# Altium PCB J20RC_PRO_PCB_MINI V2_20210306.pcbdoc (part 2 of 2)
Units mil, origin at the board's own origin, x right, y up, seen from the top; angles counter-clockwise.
Board outline 5082.94 x 4658.14 mil, 2 copper layers (Top Layer, Bottom Layer); 108 components, 96 nets, 409 pads, 123 vias.
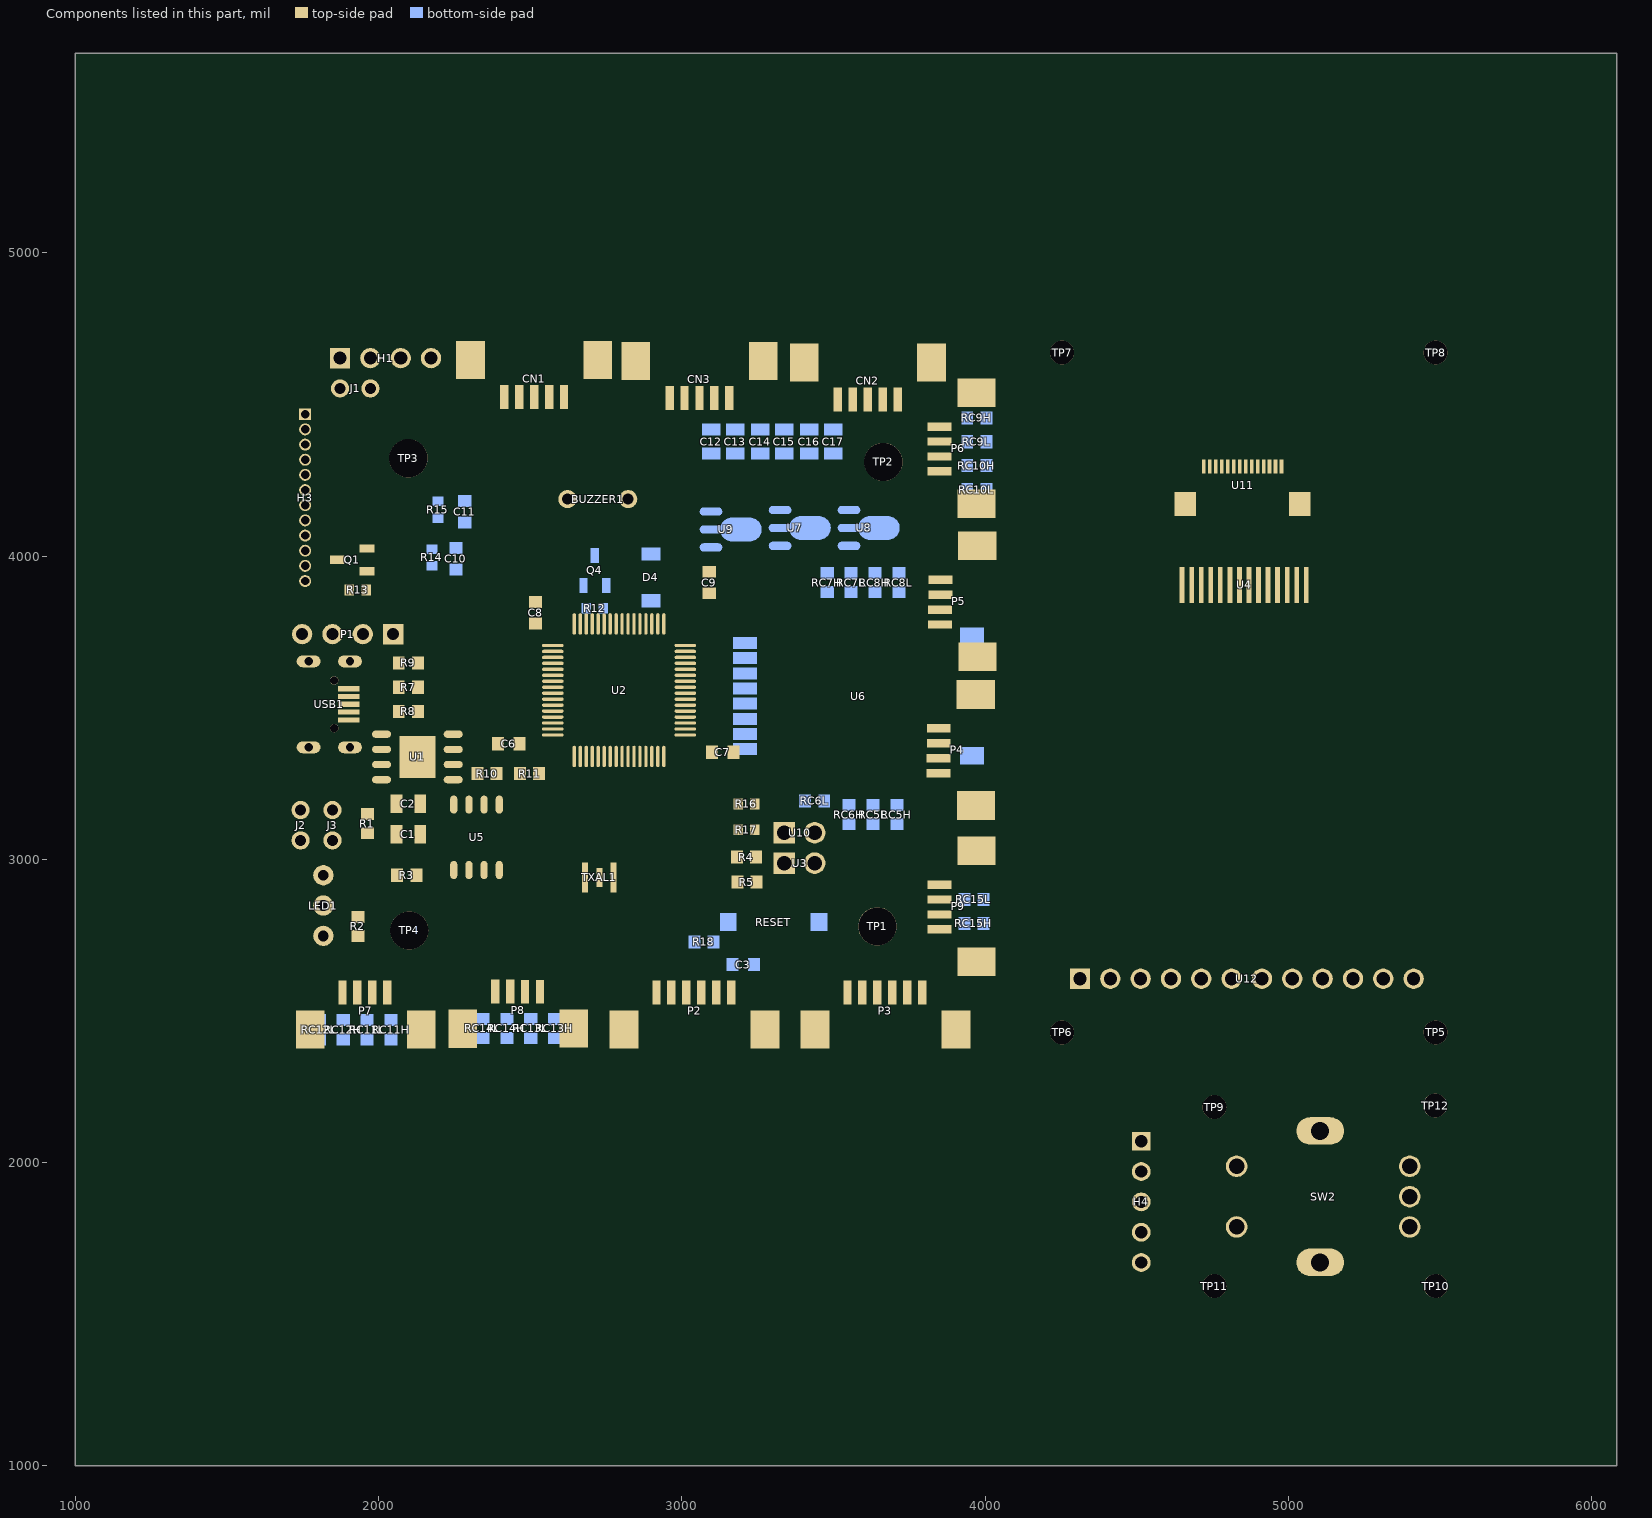
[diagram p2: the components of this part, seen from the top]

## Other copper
Top Layer:
  region net R2_1: 1840.52,2772.75 1840.29,2722.56 1863.8,2742.55 1863.85,2752.55
  region net R3_1: 1840.41,2972.85 1840.4,2922.65 1863.83,2942.75 1863.83,2952.75
  region net U1_5: 1763.11,3185.26 1763.11,3140.26 1784.11,3157.76 1784.11,3167.76
  region net U1_5: 1828.43,3140.26 1828.42,3185.26 1807.42,3167.76 1807.43,3157.76
  region net PPM: 1993.12,4575.25 1993.11,4530.25 2014.11,4547.75 2014.11,4557.75
  region net LCD_A0: 1771.29,4182.52 1771.28,4152.99 1785.07,4162.75 1785.07,4172.75
  region net LCD_SDA: 1771.29,4232.52 1771.28,4202.99 1785.07,4212.75 1785.07,4222.75
  region net LCD_SCK: 1771.29,4282.52 1771.28,4252.99 1785.07,4262.75 1785.07,4272.75
  region net LCD_CS: 1771.29,4432.52 1771.28,4402.99 1785.07,4412.75 1785.07,4422.75
  region net LCD_RST: 1771.29,4132.52 1771.28,4102.99 1785.07,4112.75 1785.07,4122.75
  region net LCD_LED-: 1771.29,3982.52 1771.28,3952.99 1785.07,3962.75 1785.07,3972.75
  region net VCC_MCU: 3461.71,3114.33 3461.7,3061.18 3486.51,3082.76 3486.51,3092.76
  region net VCC_LCD: 2845.77,4207.6 2800.77,4207.6 2818.27,4228.6 2828.27,4228.6
  region net 2SL: 3104.27,3100.69 3122.27,3100.69 3118.27,3109.09 3108.27,3109.09
  region net 2SL: 3125.24,3093.5 3112.51,3080.78 3121.28,3077.67 3128.35,3084.73
  region net 2SL: 2999.01,3239.73 2986.29,3227 2983.18,3235.77 2990.24,3242.84
  region net 1SL: 3174.27,2919.82 3192.27,2919.82 3188.27,2911.42 3178.27,2911.42
  region net 1SL: 2942.14,3444.7 2931.56,3430.14 2927.08,3438.27 2933.03,3446.46
  region net CH16: 2820.34,3393.75 2820.33,3411.75 2811.93,3407.75 2811.93,3397.75
  region net CH16: 3044.27,3249.82 3062.27,3249.82 3058.27,3241.42 3048.27,3241.42
  region net NRF_IRQ: 3200.34,3654.46 3200.32,3672.46 3191.92,3668.45 3191.94,3658.45
  region net NRF_CE: 3379.02,3630.78 3366.29,3643.5 3363.18,3634.73 3370.26,3627.67
  region net NRF_MISO: 2889.27,3595.69 2907.27,3595.69 2903.27,3604.09 2893.27,3604.09
  region net NRF_MOSI: 2885.24,3617 2872.52,3629.73 2878.33,3629.89 2885.4,3622.81
  region net NRF_SCK: 2914.27,3645.69 2932.27,3645.69 2928.27,3654.09 2918.27,3654.09
  region net NRF_CSN: 2936.65,3685.76 2952.69,3693.91 2945.87,3699.86 2935.87,3694.78
  region net RX_BM_SW: 3024.02,4200.78 3011.29,4213.5 3008.18,4204.73 3015.26,4197.67
  region net RX_BM_SW: 3094.27,4280.69 3112.27,4280.69 3108.27,4289.09 3098.27,4289.09
  region net EEPROM_SCL: 2390.52,3270.78 2377.78,3283.5 2374.68,3274.73 2381.75,3267.66
  region net EEPROM_SCL: 2421.16,3459.57 2419.88,3477.53 2428.54,3474.15 2429.25,3464.15
  region net BM_CLK: 2194.27,3834.82 2212.27,3834.82 2208.27,3826.42 2198.27,3826.42
  region net VCC_MCU: 2640.24,3983.5 2627.51,3970.78 2636.28,3967.67 2643.35,3974.74
  region net SWDIO: 2680.24,3682 2667.52,3694.73 2676.29,3697.84 2683.36,3690.77
  region net USB_DP: 2680.24,3647 2667.52,3659.73 2676.29,3662.84 2683.36,3655.77
  region net USB_DM: 2680.24,3612 2667.52,3624.73 2676.29,3627.84 2683.36,3620.77
  region net SWCLK: 2456.21,3731.75 2456.2,3713.75 2464.6,3717.75 2464.61,3727.75
  region net LCD_LED: 2449.56,3428.26 2449.52,3446.26 2441.13,3442.25 2441.15,3432.25
  region net LCD_LED: 2673.21,3451.04 2655.36,3448.73 2660.37,3440.91 2670.37,3442.2
  region net BEEPER: 2749.02,3435.78 2736.29,3448.5 2733.18,3439.73 2740.26,3432.67
  region net U1_7: 2203.92,2907.19 2191.17,2919.9 2188.07,2911.13 2195.16,2904.07
  region net +5V: 2256.28,3421.69 2238.41,3419.59 2241.37,3428.4 2251.37,3429.57
  region net U1_5: 2011.21,3236.75 2011.2,3218.75 2019.6,3222.75 2019.61,3232.75
  region net VM: 3438.46,3573.75 3432.96,3556.61 3426.11,3562.75 3429.32,3572.75
  region net VM: 3438.46,3573.75 3432.96,3556.61 3426.11,3562.75 3429.32,3572.75
  region net VM: 3248.42,3176.35 3230.64,3173.49 3235.87,3165.82 3245.87,3167.43
  region net BM_CLK: 2968,4244.77 2950.09,4246.54 2954.87,4254.51 2964.87,4253.52
  region net CH15: 3074.27,3269.82 3092.27,3269.82 3088.27,3261.42 3078.27,3261.42
  region net CH15: 2909.27,3495.69 2927.27,3495.69 2923.27,3504.09 2913.27,3504.09
  region net BAT+: 3658.76,4100.69 3640.76,4100.7 3644.76,4109.1 3654.76,4109.09
  region net BAT+: 3658.26,4173.18 3640.29,4172.14 3644.76,4163.99 3654.76,4164.57
  region net CH8: 3840.34,3863.75 3840.33,3881.75 3831.93,3877.75 3831.93,3867.75
  region net CH7: 3843.93,3814.45 3843.92,3832.45 3835.53,3828.45 3835.53,3818.45
  region net CH10: 3840.34,4368.75 3840.33,4386.75 3831.93,4382.75 3831.93,4372.75
  region net CH9: 3942.01,4365.06 3929.28,4377.79 3926.17,4369.02 3933.24,4361.95
  region net CH9: 3950.26,4369.11 3932.26,4369.09 3936.27,4360.7 3946.27,4360.7
  region net VCC_MCU: 3996.33,4446.76 3996.3,4464.76 3987.9,4460.75 3987.92,4450.75
  region net VCC_MCU: 4013.25,4447.84 3995.25,4447.84 3999.24,4439.44 4009.24,4439.44
  region net VCC_MCU: 4013.25,4306.24 3995.25,4306.23 3999.24,4314.63 4009.24,4314.64
  region net VCC_MCU: 3519.27,4235.69 3537.27,4235.69 3533.27,4244.09 3523.27,4244.09
  region net VCC_MCU: 3529.02,4215.78 3516.29,4228.51 3513.18,4219.74 3520.25,4212.67
  region net VCC_MCU: 3529.02,4215.78 3516.29,4228.5 3513.18,4219.73 3520.26,4212.67
  region net VCC_MCU: 3470.53,3952.19 3488.53,3952.19 3484.53,3960.59 3474.53,3960.59
  region net VCC_MCU: 3092.78,3865.77 3081.43,3879.74 3077.41,3871.37 3083.75,3863.56
  region net VCC_MCU: 3101.21,3886.75 3101.2,3868.75 3109.6,3872.75 3109.61,3882.75
  region net BAT+: 3244.02,4014.73 3231.29,4002 3228.18,4010.77 3235.25,4017.84
  region net BAT+: 3184.27,4079.82 3202.27,4079.82 3198.27,4071.42 3188.27,4071.42
  region net VCC_MCU: 3699.27,3125.69 3717.27,3125.69 3713.27,3134.09 3703.27,3134.09
  region net CH5: 3835.78,3342.13 3834.9,3324.15 3826.71,3328.55 3827.19,3338.55
  region net CH6: 3835.34,3373.75 3835.33,3391.75 3826.93,3387.75 3826.93,3377.75
  region net VCC_MCU: 3943.76,2788.27 3931.03,2800.99 3939.79,2804.11 3946.87,2797.04
  region net VCC_MCU: 3940.77,2781.07 3922.77,2781.09 3926.77,2772.68 3936.77,2772.68
  region net CH15: 3989.27,2935.69 4007.27,2935.69 4003.27,2944.09 3993.27,2944.09
  region net U2_5: 2594.95,3174.29 2610.12,3164.61 2611.37,3173.78 2602.73,3179.29
  region net U2_6: 2657.84,3171.96 2639.84,3172.01 2643.87,3180.4 2653.87,3180.37
  region net U2_7: 2710.41,3208.17 2697.69,3220.9 2706.46,3224.01 2713.52,3216.93
  region net CH14: 2474.27,2571.5 2492.27,2571.5 2488.27,2579.9 2478.27,2579.9
  region net CH13: 2502.74,2486.24 2490.03,2473.49 2486.91,2482.25 2493.97,2489.34
  region net VCC_MCU: 2569.27,2415.69 2587.27,2415.69 2583.27,2424.09 2573.27,2424.09
  region net VCC_MCU: 3022.65,2556.32 3004.87,2553.52 3010.07,2545.83 3020.07,2547.41
  region net CH12: 1891.76,2478.76 1891.73,2460.76 1900.14,2464.75 1900.15,2474.75
  region net VCC_MCU: 2034.27,2415.69 2052.27,2415.69 2048.27,2424.09 2038.27,2424.09
  region net VCC_NRF: 3320.24,3362 3307.52,3374.73 3316.29,3377.84 3323.36,3370.77
  region net VCC_NRF: 3551.41,3364.61 3566.59,3374.29 3558.81,3379.29 3550.17,3373.78
  region net BAT+: 1930.24,2913.51 1917.52,2900.78 1924.73,2899.22 1931.8,2906.29
  region net BAT+: 1995.33,2893.76 1995.33,2911.76 1986.93,2907.76 1986.93,2897.76
  region net PPM: 2735.24,3532 2722.52,3544.73 2731.29,3547.84 2738.36,3540.77
  region net PPM: 2359.27,3965.69 2377.27,3965.69 2373.27,3974.09 2363.27,3974.09
  region net TX_BM_DT: 2700.24,3542 2687.52,3554.73 2696.29,3557.84 2703.36,3550.77
  region net VCC_MCU: 2085.24,4168.51 2072.52,4155.78 2081.28,4152.67 2088.35,4159.74
  region net VCC_MCU: 2186.55,4115.68 2186.55,4133.68 2178.15,4129.68 2178.15,4119.68
  region net TX_BM_DT: 1959.51,4319.89 1977.51,4319.89 1973.51,4311.49 1963.51,4311.49
  region net TX_BM_DT: 1959.51,4319.89 1977.51,4319.89 1973.51,4311.49 1963.51,4311.49
  region net TX_BM_DT: 2137.07,4082.35 2125.1,4068.91 2121.48,4077.47 2128.14,4084.95
  region net VCC_MCU: 2845.24,3448.5 2832.51,3435.78 2841.28,3432.67 2848.35,3439.73
  region net VCC_MCU: 2567.96,3371.21 2555.22,3383.93 2552.11,3375.16 2559.19,3368.1
  region net VCC_MCU: 2562.9,3394.39 2578.85,3386.05 2579.77,3395.05 2569.77,3400.28
  region net VCC_MCU: 2624.27,3684.82 2642.27,3684.82 2638.27,3676.42 2628.27,3676.42
  region net VCC_MCU: 2624.27,3700.69 2642.27,3700.69 2638.27,3709.09 2628.27,3709.09
  region net VCC_MCU: 2779.02,3505.78 2766.29,3518.51 2764.73,3511.29 2771.8,3504.22
  region net VCC_MCU: 3954.27,2909.82 3972.27,2909.82 3968.27,2902.76 3958.27,2902.76
  region net VCC_MCU: 3140.34,3703.75 3140.33,3721.75 3131.93,3717.75 3131.93,3707.75
  region net VCC_MCU: 3117.29,3430.35 3104.56,3417.63 3101.45,3426.39 3108.52,3433.47
  region net VCC_MCU: 3128.52,3419.13 3115.79,3406.4 3124.56,3403.29 3131.63,3410.36
  region net VCC_LCD: 2805.24,4273.51 2792.52,4260.78 2801.28,4257.67 2808.35,4264.74
  region net USB1_3: 2065.82,3499.48 2051.32,3488.82 2049.52,3497.93 2057.67,3503.92
  region net RX_BM_SW: 3114.41,4507.45 3097.27,4512.96 3098.27,4503.81 3108.27,4500.6
  region net VCC_MCU: 3549.02,3100.78 3536.29,3113.51 3533.18,3104.74 3540.25,3097.67
  region net U2_5: 2690.08,3026.96 2672.08,3027 2676.07,3018.59 2686.07,3018.57
  region net U2_6: 2784.16,3028.21 2766.18,3027.36 2770.57,3019.15 2780.57,3019.63
  region net CH11: 1939.97,2617.77 1922,2618.88 1925.47,2610.25 1935.47,2609.64
  region net CH11: 1943.44,2625.46 1930.75,2638.23 1939.53,2641.31 1946.58,2634.22
  region net VCC_MCU: 3151.18,3374.68 3172.73,3374.68 3152.31,3389.68 3138.16,3389.68
  region net VCC_MCU: 3090.67,3857.75 3068.89,3870.02 3062.47,3856.42 3071.52,3851.32
  region net VCC_MCU: 3112.2,3890.25 3112.2,3865.25 3127.2,3872.75 3127.2,3882.75
  region net VCC_MCU: 2539.76,3788.75 2539.76,3763.75 2554.76,3771.25 2554.76,3781.25
  region net VCC_MCU: 2479.27,3359.72 2454.27,3359.72 2461.77,3344.72 2471.77,3344.72
  region net VM: 3253.37,3165.04 3228.37,3165.04 3235.87,3150.04 3245.87,3150.04
  region net VM: 3228.37,3115.47 3253.37,3115.47 3245.87,3130.47 3235.87,3130.47
  region net USB1_2: 2059.23,3546.1 2047.08,3567.95 2040.61,3548.73 2045.66,3539.64
  region net R3_1: 2042.09,2935.25 2042.09,2960.25 2027.09,2952.75 2027.09,2942.75
  region net U1_2: 1950.77,3168.94 1975.77,3168.94 1968.27,3183.94 1958.27,3183.94
  region net USB1_3: 2047.08,3487.63 2059.35,3509.41 2046.8,3514.78 2040.72,3506.73
  region net 2SL: 3164.11,3029.41 3189.11,3029.41 3168.68,3044.41 3154.54,3044.41
  region net 1SL: 3195.77,2903.7 3170.77,2903.7 3178.27,2888.7 3188.27,2888.7
  region net +5V: 2086.46,3647.85 2074.14,3626.1 2087.75,3619.69 2092.86,3628.72
  region net +5V: 2047.09,3635.25 2047.09,3660.25 2032.09,3652.75 2032.09,3642.75
  region net U1_7: 1953.94,2823.05 1953.94,2798.05 1968.94,2805.55 1968.94,2815.55
  region net R2_1: 1910.63,2735.05 1910.63,2760.05 1895.63,2752.55 1895.63,2742.55
  region net VCC_MCU: 2447.09,3304.41 2469.11,3304.41 2448.68,3319.41 2434.54,3319.41
  region net VCC_MCU: 2474.19,3304.41 2486.45,3282.62 2492.88,3301.79 2487.78,3310.83
  region net VCC_MCU: 2454.27,3304.41 2479.27,3304.41 2471.77,3319.41 2461.77,3319.41
  region net EEPROM_SDA: 2537.2,3304.41 2549.44,3282.61 2555.88,3301.79 2550.79,3310.84
  region net EEPROM_SDA: 2522.4,3261.1 2510.07,3282.85 2503.67,3263.72 2508.79,3254.7
  region net VCC_MCU: 2334.19,3304.41 2346.45,3282.62 2352.88,3301.79 2347.78,3310.83
  region net VCC_MCU: 2319.39,3261.1 2307.08,3282.86 2300.67,3263.72 2305.78,3254.69
  region net EEPROM_SCL: 2382.4,3261.1 2370.07,3282.85 2363.67,3263.72 2368.79,3254.7
  region net LCD_LED-: 1862.79,3973.97 1839.46,3973.97 1840.53,3971.28 1851.14,3967.75
  region net Q1_1: 1971.57,3936.57 1946.57,3936.57 1954.07,3921.57 1964.07,3921.57
  region net U1_5: 2117.95,3189.96 2117.95,3213.27 2102.95,3224.53 2102.95,3210.39
  region net U1_5: 2157.32,3213.27 2157.32,3189.9 2172.32,3210.33 2172.32,3224.47
  region net LCD_LED: 1919.7,3892.53 1907.51,3870.7 1921.08,3864.24 1926.15,3873.32
  region net Q1_1: 1946.57,3906.13 1971.57,3906.13 1964.07,3921.13 1954.07,3921.13
  region net CH3_DOWN: 2574.97,4485.01 2549.97,4485.01 2557.47,4470.01 2567.47,4470.01
  region net CH4_RIGHT: 2427.37,4485.01 2402.37,4485.01 2409.87,4470.01 2419.87,4470.01
  region net CH4_LEFT: 2476.57,4485.01 2451.57,4485.01 2459.07,4470.01 2469.07,4470.01
  region net CH3_UP: 2525.77,4485.01 2500.77,4485.01 2508.27,4470.01 2518.27,4470.01
  region net VCC_MCU: 3799.73,2521.71 3778.67,2521.71 3765.16,2506.71 3779.3,2506.71
  region net VCC_MCU: 3779.97,2600.45 3804.97,2600.45 3797.47,2615.45 3787.47,2615.45
  region net CH4: 3730.77,2600.45 3755.77,2600.45 3748.27,2602.75 3738.27,2602.75
  region net VCC_MCU: 3658.59,2522.24 3636.27,2522.24 3656.7,2507.24 3670.84,2507.24
  region net VCC_MCU: 3652.38,2522.24 3631.02,2535.24 3624.85,2521.44 3633.64,2516.09
  region net CH3: 3583.07,2600.99 3608.07,2600.99 3600.57,2615.45 3590.57,2615.45
  region net VCC_MCU: 3169.73,2521.71 3148.96,2521.71 3135.16,2506.71 3149.3,2506.71
  region net VCC_MCU: 3176.52,2573.55 3176.52,2548.55 3191.52,2556.05 3191.52,2566.05
  region net CH2: 3101.07,2600.45 3126.07,2600.45 3118.57,2615.45 3108.57,2615.45
  region net VCC_MCU: 3027.57,2522.24 3002.57,2522.24 3010.07,2520.95 3020.07,2520.95
  region net CH1: 2953.37,2600.99 2978.37,2600.99 2970.87,2615.99 2960.87,2615.99
  region net USB1_3: 1937.24,3519.76 1937.24,3502.83 1952.24,3506.25 1952.24,3516.25
  region net USB1_2: 1937.24,3545.36 1937.24,3528.43 1952.24,3531.95 1952.24,3541.95
  region net +5V: 1897.69,3570.96 1922.69,3570.96 1932.28,3585.96 1918.13,3585.96
  region net VCC_MCU: 2546.23,2562.29 2546.23,2537.29 2561.23,2527.72 2561.23,2541.86
  region net CH14: 2470.77,2602.95 2495.77,2602.95 2488.27,2617.95 2478.27,2617.95
  region net CH13: 2447.79,2548.65 2440.48,2524.74 2453.43,2515.79 2456.74,2526.62
  region net CH13: 2421.47,2603.49 2446.47,2603.49 2438.97,2618.49 2428.97,2618.49
  region net VCC_MCU: 2039.74,2543.2 2042.68,2552.04 2042.68,2559.83 2043.27,2553.8 2042.68,2552.04 2042.68,2534.83 2039.74,2543.2
  region net CH12: 1985.86,2521.73 1965.92,2521.73 1951.32,2506.73 1965.45,2506.73
  region net CH12: 1967.17,2600.47 1992.17,2600.47 1984.67,2613.05 1974.67,2613.05
  region net CH11: 1917.97,2601 1942.97,2601 1935.47,2616 1925.47,2616
  region net VCC_MCU: 3810.57,4414.45 3810.57,4439.45 3795.57,4431.95 3795.57,4421.95
  region net VCC_MCU: 3851.23,4440.71 3876.23,4440.71 3885.8,4455.71 3871.66,4455.71
  region net CH10: 3812.66,4363.95 3810.57,4388.87 3797.61,4364.01 3798.7,4350.95
  region net CH9: 3888.78,4341.05 3888.78,4316.05 3892.77,4323.55 3892.77,4333.55
  region net CH8: 3813.07,3860.25 3813.07,3885.25 3798.07,3877.75 3798.07,3867.75
  region net CH7: 3812.54,3810.95 3812.54,3835.95 3797.54,3828.45 3797.54,3818.45
  region net CH6: 3808.07,3370.25 3808.07,3395.25 3793.07,3387.75 3793.07,3377.75
  region net CH5: 3807.54,3321.05 3807.54,3346.05 3792.54,3338.55 3792.54,3328.55
  region net CH15: 3889.31,2881.51 3889.31,2861.29 3904.31,2881.72 3904.31,2895.86
  region net CH15: 3810.57,2855.25 3810.57,2880.25 3795.57,2872.75 3795.57,2862.75
  region net CH16: 3810.04,2806.05 3810.04,2831.05 3795.04,2823.55 3795.04,2813.55
  region net CH1_LEFT: 3674.97,4477.51 3649.97,4477.51 3657.47,4462.51 3667.47,4462.51
  region net CH2_UP: 3525.77,4477.51 3501.06,4477.51 3508.27,4462.51 3518.27,4462.51
  region net CH2_DOWN: 3576.57,4477.51 3551.57,4477.51 3559.07,4462.51 3569.07,4462.51
  region net CH1_RIGHT: 3625.77,4477.51 3600.77,4477.51 3608.27,4462.51 3618.27,4462.51
  region net RX_BM_SW: 3115.77,4482.51 3093.7,4482.51 3098.27,4467.51 3108.27,4467.51
  region net BM_CLK: 2972.37,4482.51 2947.37,4482.51 2954.87,4467.51 2964.87,4467.51
  region net TX_BM_DT: 3070.77,4482.51 3045.77,4482.51 3053.27,4467.51 3063.27,4467.51
  region net 2SL: 3325.77,3123.19 3350.77,3123.19 3343.27,3138.19 3333.27,3138.19
  region net 1SL: 3350.77,2952.32 3325.77,2952.32 3333.27,2937.32 3343.27,2937.32
  region net U2_5: 2671.31,2989.64 2690.98,2989.64 2686.07,3004.64 2676.07,3004.64
  region net U2_6: 2765.7,2989.64 2785.38,2989.64 2780.57,3004.64 2770.57,3004.64
  region net U1_5: 2230.7,3251.65 2222.68,3273.87 2210.71,3262.86 2214.46,3252.47
  region net +5V: 2233.87,3424.57 2258.87,3424.57 2251.37,3439.57 2241.37,3439.57
  region net U1_2: 1990.48,3350.95 1990.46,3374.57 1978.26,3367.75 1978.27,3357.75
  region net EEPROM_SDA: 2410.08,3193.15 2410.08,3168.15 2425.08,3175.65 2425.08,3185.65
  region net EEPROM_SCL: 2360.08,3198.74 2336.46,3198.74 2343.27,3213.74 2353.27,3213.74
  region net VCC_MCU: 2258.5,3192.84 2238.03,3204.63 2251.27,3214.32 2260.24,3209.15
  region net VCC_MCU: 2587.27,3404.61 2562.27,3404.61 2569.77,3390.75 2579.77,3390.75
  region net EEPROM_SDA: 2604.7,3455 2604.67,3443.98 2619.68,3444.45 2619.7,3454.45
  region net EEPROM_SCL: 2544.86,3463.67 2544.83,3474.69 2529.84,3474.15 2529.85,3464.15
  region net 2SL: 2604.69,3494.37 2604.69,3483.35 2619.69,3483.85 2619.69,3493.85
  region net 2SL: 2604.69,3494.37 2604.69,3483.35 2619.69,3483.85 2619.69,3493.85
  region net BM_CLK: 2544.85,3503.04 2544.85,3514.06 2529.85,3513.55 2529.85,3503.55
  region net LCD_RST: 2544.85,3533.74 2544.84,3522.72 2529.84,3523.25 2529.85,3533.25
  region net LCD_A0: 2544.86,3553.43 2544.83,3542.41 2529.84,3542.95 2529.85,3552.95
  region net LCD_SDA: 2544.86,3562.09 2544.83,3573.11 2529.83,3572.55 2529.86,3562.55
  region net LCD_SCK: 2544.86,3581.78 2544.83,3592.8 2529.83,3592.25 2529.86,3582.25
  region net LCD_CS: 2544.85,3601.46 2544.84,3612.48 2529.84,3611.95 2529.85,3601.95
  region net CH4_RIGHT: 2544.85,3621.15 2544.84,3632.17 2529.84,3631.65 2529.85,3621.65
  region net CH4_LEFT: 2544.85,3651.85 2544.84,3640.83 2529.84,3641.35 2529.85,3651.35
  region net CH3_UP: 2544.85,3671.54 2544.84,3660.52 2529.84,3661.05 2529.85,3671.05
  region net CH3_DOWN: 2544.87,3680.2 2544.82,3691.22 2529.82,3690.65 2529.87,3680.65
  region net SWCLK: 2556.7,3710.91 2581.7,3710.91 2564.44,3722.75 2553.83,3719.21
  region net VCC_MCU: 2640.11,3758.19 2640.11,3783.19 2633.27,3770.92 2636.8,3760.31
  region net VCC_MCU: 2651.14,3806.16 2640.11,3806.19 2640.67,3821.19 2650.67,3821.16
  region net VCC_MCU: 2640.11,3763.75 2640.11,3788.75 2625.11,3781.25 2625.11,3771.25
  region net SWDIO: 2690.51,3746.33 2679.48,3746.35 2679.97,3731.35 2689.97,3731.33
  region net USB_DP: 2710.2,3746.33 2699.18,3746.34 2699.67,3731.34 2709.67,3731.33
  region net USB_DM: 2729.88,3746.34 2718.85,3746.34 2719.37,3731.34 2729.37,3731.34
  region net RX_BM_SW: 2749.57,3806.17 2738.55,3806.18 2739.07,3821.18 2749.07,3821.17
  region net TX_BM_DT: 2769.25,3806.17 2758.22,3806.19 2758.77,3821.19 2768.77,3821.17
  region net TX_BM_DT: 2769.25,3746.35 2758.22,3746.33 2758.77,3731.33 2768.77,3731.35
  region net PPM: 2788.94,3746.35 2777.92,3746.32 2778.47,3731.32 2788.47,3731.35
  region net CH2_UP: 2808.62,3806.19 2797.59,3806.16 2798.07,3821.16 2808.07,3821.19
  region net CH2_DOWN: 2828.31,3806.19 2817.29,3806.17 2817.77,3821.17 2827.77,3821.19
  region net CH1_RIGHT: 2847.99,3806.18 2836.97,3806.17 2837.47,3821.17 2847.47,3821.18
  region net CH1_LEFT: 2867.68,3806.18 2856.66,3806.18 2857.17,3821.18 2867.17,3821.18
  region net NRF_MOSI: 2887.36,3746.34 2876.34,3746.33 2876.87,3731.33 2886.87,3731.34
  region net NRF_MISO: 2907.05,3762.27 2899.74,3741.13 2898.16,3712.16 2907.7,3730.72
  region net NRF_CSN: 2946.42,3746.32 2935.4,3746.35 2935.87,3731.35 2945.87,3731.32
  region net VCC_MCU: 3004.83,3710.91 3012.1,3712.75 3017.61,3710.91 3029.83,3710.91 3022.7,3709.21 3017.61,3710.91 3004.83,3710.91
  region net VCC_MCU: 2999.27,3710.91 3024.27,3710.91 3016.77,3725.91 3006.77,3725.91
  region net NRF_CE: 3041.69,3640.83 3041.69,3651.85 3056.69,3651.35 3056.69,3641.35
  region net CH10: 3041.7,3612.48 3041.68,3601.46 3056.68,3601.95 3056.7,3611.95
  region net CH9: 3041.71,3592.8 3041.68,3581.78 3056.68,3582.25 3056.7,3592.25
  region net VM: 3041.75,3562.09 3041.64,3573.11 3056.64,3572.75 3056.74,3562.75
  region net VM: 3041.75,3562.09 3041.64,3573.11 3056.64,3572.75 3056.74,3562.75
  region net CH15: 2981.86,3553.43 2981.84,3542.41 2966.84,3542.95 2966.86,3552.95
  region net CH8: 3041.7,3522.72 3041.68,3533.74 3056.68,3533.25 3056.7,3523.25
  region net CH7: 3041.69,3503.04 3041.69,3514.06 3056.69,3513.55 3056.69,3503.55
  region net CH6: 3041.69,3494.37 3041.69,3483.35 3056.69,3483.85 3056.69,3493.85
  region net CH5: 3041.7,3474.69 3041.68,3463.67 3056.68,3464.15 3056.7,3474.15
  region net VCC_MCU: 3041.71,3455 3041.68,3443.98 3056.68,3444.45 3056.7,3454.45
  region net VCC_MCU: 3041.71,3455 3041.68,3443.98 3056.68,3444.45 3056.7,3454.45
  region net CH4: 3029.81,3404.61 3004.81,3404.61 3016.2,3398.65 3026.8,3402.18
  region net CH3: 2946.42,3309.32 2935.4,3309.35 2935.87,3294.35 2945.87,3294.32
  region net CH2: 2926.73,3309.32 2915.71,3309.36 2916.17,3294.35 2926.17,3294.32
  region net CH1: 2907.05,3309.35 2896.03,3309.33 2896.57,3294.33 2906.57,3294.35
  region net VCC_MCU: 2887.36,3369.17 2876.34,3369.19 2876.87,3384.18 2886.87,3384.17
  region net CH14: 2847.99,3309.33 2836.97,3309.34 2837.47,3294.34 2847.47,3294.33
  region net CH13: 2828.31,3309.51 2817.29,3309.16 2818.27,3294.19 2828.27,3294.5
  region net CH12: 2808.62,3309.32 2797.59,3309.35 2798.07,3294.35 2808.07,3294.32
  region net CH11: 2788.94,3309.35 2777.92,3309.32 2778.47,3294.32 2788.47,3294.35
  region net U2_7: 2769.25,3309.35 2758.22,3309.33 2758.77,3294.33 2768.77,3294.35
  region net U2_6: 2749.57,3309.34 2738.55,3309.33 2739.07,3294.33 2749.07,3294.34
  region net U2_5: 2729.88,3309.34 2718.85,3309.34 2719.37,3294.34 2729.37,3294.34
  region net BEEPER: 2690.51,3369.19 2679.48,3369.17 2679.97,3384.17 2689.97,3384.19
  region net LCD_LED: 2670.83,3369.16 2659.81,3369.2 2660.37,3384.19 2670.37,3384.16
  region net U4_2: 4300.47,2640.07 4325.47,2640.07 4317.97,2655.07 4307.97,2655.07
  region net U4_2: 4689.02,3846.02 4673.26,3846.02 4676.17,3831.02 4686.17,3831.02
  region net U4_3: 4438.08,2628.71 4387.88,2628.7 4407.97,2652.13 4417.97,2652.13
  region net U4_3: 4720.51,3846.02 4704.77,3846.02 4707.64,3831.02 4717.64,3831.02
  region net U4_4: 4752,3846.02 4736.26,3846.02 4739.13,3831.02 4749.13,3831.02
  region net U4_4: 4489.68,2630.59 4539.73,2626.69 4521.53,2651.6 4511.53,2652.38
  region net U4_5: 4638.08,2628.71 4587.88,2628.7 4607.97,2652.13 4617.97,2652.13
  region net U4_5: 4783.5,3846.02 4767.76,3846.02 4770.63,3831.02 4780.63,3831.02
  region net U4_6: 4815,3846.02 4799.25,3846.02 4802.13,3831.02 4812.13,3831.02
  region net U4_6: 4738.27,2628.49 4688.08,2628.92 4708.38,2652.17 4718.38,2652.09
  region net U4_11: 4972.48,3846.02 4956.73,3846.02 4959.61,3831.02 4969.61,3831.02
  region net U4_11: 5237.1,2629.77 5186.95,2627.6 5206.02,2651.87 5216.02,2652.3
  region net U4_12: 5338.08,2628.71 5287.88,2628.7 5307.97,2652.13 5317.97,2652.13
  region net U4_12: 5003.97,3846.02 4988.22,3846.02 4991.1,3831.02 5001.1,3831.02
  region net U4_13: 5035.48,3846.02 5019.72,3846.02 5022.6,3831.02 5032.6,3831.02
  region net U4_13: 5438.08,2628.71 5387.89,2628.71 5407.98,2652.13 5417.98,2652.13
  region net U4_10: 4940.97,3846.05 4925.27,3846.05 4928.07,3831.05 4938.07,3831.05
  region net U4_10: 5138.08,2628.71 5087.88,2628.7 5107.97,2652.13 5117.97,2652.13
  region net U4_9: 5038.08,2628.71 4987.88,2628.7 5007.97,2652.13 5017.97,2652.13
  region net U4_9: 4909.47,3846.05 4893.77,3846.05 4896.57,3831.05 4906.57,3831.05
  region net U4_7: 4846.47,3846.05 4830.77,3846.05 4833.67,3831.05 4843.67,3831.05
  region net U4_7: 4838.08,2628.71 4787.88,2628.7 4807.97,2652.13 4817.97,2652.13
  region net U4_8: 4938.08,2628.71 4887.88,2628.7 4907.97,2652.13 4917.97,2652.13
  region net U4_8: 4877.97,3846.05 4862.27,3846.05 4865.17,3831.05 4875.17,3831.05
Bottom Layer:
  region net +5V: 1840.41,2872.85 1840.4,2822.66 1863.83,2842.75 1863.83,2852.75
  region net SWCLK: 1881.73,3743.26 1843.59,3775.89 1874.08,3780.64 1881.7,3774.11
  region net SWDIO: 1981.59,3739.64 1941.01,3710.09 1971,3702.95 1979.18,3708.91
  region net BAT+: 1846.39,3032.82 1878.21,3064.63 1880.68,3037.41 1873.61,3030.34
  region net U1_5: 1846.39,3192.7 1878.21,3160.88 1880.69,3188.1 1873.61,3195.17
  region net VCC_MCU: 1939.87,4654.85 1975.36,4619.36 1944.59,4617.01 1937.52,4624.08
  region net TX_BM_DT: 2098.37,4630.62 2048.17,4630.62 2068.27,4607.2 2078.27,4607.2
  region net RX_BM_SW: 2200.37,4672.38 2189.35,4623.41 2216.59,4637.76 2218.84,4647.76
  region net VCC_LCD: 1773.03,4354.74 1743.5,4354.74 1753.27,4340.96 1763.27,4340.96
  region net VCC_LCD: 1738.62,4318.99 1759.5,4298.11 1742.85,4295.27 1735.78,4302.34
  region net VCC_LCD: 1773.03,4330.78 1743.5,4330.78 1753.27,4344.56 1763.27,4344.56
  region net VCC_LCD: 1738.63,4019.13 1762.08,4037.07 1745.99,4042.11 1737.98,4035.98
  region net VCC_LCD: 1757.04,4037.4 1777.91,4016.52 1780.76,4033.17 1773.69,4040.24
  region net VCC_LCD: 2845.77,4167.91 2800.77,4167.91 2818.27,4146.91 2828.27,4146.91
  region net D4_1: 2621.38,4157.82 2653.21,4189.63 2655.68,4162.41 2648.61,4155.34
  region net 2SL: 3104.27,3100.69 3122.27,3100.69 3118.27,3109.09 3108.27,3109.09
  region net 2SL: 3010.24,3228.51 2997.52,3215.78 3006.28,3212.67 3013.35,3219.74
  region net 1SL: 3175.33,2918.76 3175.33,2936.76 3166.93,2932.76 3166.93,2922.76
  region net 1SL: 2951.21,3423.76 2951.2,3441.76 2959.61,3437.76 2959.6,3427.76
  region net 1SL: 2951.21,3423.76 2951.2,3441.76 2959.61,3437.76 2959.6,3427.76
  region net CH16: 2836.21,3393.76 2836.2,3411.76 2844.61,3407.76 2844.6,3397.76
  region net CH16: 3045.33,3248.76 3045.33,3266.76 3038.27,3262.76 3038.27,3252.76
  region net NRF_CE: 3369.27,3634.82 3387.27,3634.82 3383.27,3626.42 3373.27,3626.42
  region net NRF_MISO: 2906.25,3596.72 2906.16,3578.72 2914.58,3582.67 2914.63,3592.67
  region net NRF_MOSI: 2883.58,3623.89 2878.06,3606.76 2887.21,3607.75 2890.43,3617.75
  region net NRF_SCK: 2931.21,3646.75 2931.2,3628.75 2939.6,3632.75 2939.61,3642.75
  region net NRF_CSN: 2956.33,3691.64 2956.08,3673.65 2964.53,3677.53 2964.67,3687.53
  region net RX_BM_SW: 3035.24,4212 3022.52,4224.73 3031.29,4227.84 3038.36,4220.77
  region net RX_BM_SW: 3095.34,4263.75 3095.33,4281.75 3086.93,4277.75 3086.93,4267.75
  region net +5V: 2128.64,3090.69 2146.64,3090.69 2142.64,3099.09 2132.64,3099.09
  region net +5V: 2138.39,3070.78 2125.66,3083.51 2122.55,3074.74 2129.62,3067.67
  region net EEPROM_SCL: 2401.73,3282 2389.01,3294.73 2397.78,3297.84 2404.85,3290.77
  region net EEPROM_SCL: 2403.6,3460.05 2421.6,3460.05 2417.6,3451.65 2407.6,3451.65
  region net BM_CLK: 2204.01,3854.73 2191.29,3842 2188.18,3850.77 2195.24,3857.84
  region net VCC_MCU: 2620.34,3973.75 2620.33,3991.75 2611.93,3987.75 2611.93,3977.75
  region net SWDIO: 2669.02,3670.78 2656.29,3683.51 2653.18,3674.74 2660.25,3667.67
  region net USB_DP: 2660.34,3638.75 2660.33,3656.75 2651.93,3652.75 2651.93,3642.75
  region net USB_DM: 2660.34,3603.75 2660.33,3621.75 2651.93,3617.75 2651.93,3607.75
  region net USB_DP: 2136.21,3496.75 2136.2,3478.75 2144.6,3482.75 2144.61,3492.75
  region net USB_DM: 2129.02,3555.78 2116.29,3568.5 2113.18,3559.73 2120.26,3552.67
  region net SWCLK: 2449.02,3734.73 2436.29,3722 2433.18,3730.77 2440.25,3737.84
  region net LCD_LED: 2469.45,3436.53 2456.73,3449.26 2465.49,3452.37 2472.57,3445.29
  region net LCD_LED: 2655.33,3448.76 2655.33,3466.76 2646.93,3462.76 2646.93,3452.76
  region net BEEPER: 2739.27,3455.69 2757.27,3455.69 2753.27,3464.09 2743.27,3464.09
  region net U1_6: 2136.74,2947.01 2124.02,2959.73 2132.78,2962.85 2139.85,2955.77
  region net U1_6: 2237.38,3304.82 2255.38,3304.82 2251.38,3296.42 2241.38,3296.42
  region net U1_7: 2215.12,2918.42 2202.4,2931.15 2211.16,2934.26 2218.24,2927.19
  region net U1_7: 2260.24,3363.51 2247.52,3350.78 2256.28,3347.67 2263.35,3354.74
  region net +5V: 2022.13,3262 2009.41,3274.73 2018.18,3277.84 2025.25,3270.77
  region net +5V: 2022.13,3263.51 2009.4,3250.78 2018.17,3247.67 2025.24,3254.74
  region net +5V: 2240.33,3403.76 2240.33,3421.76 2231.93,3417.76 2231.93,3407.76
  region net U1_5: 1995.33,3218.76 1995.33,3236.76 1986.93,3232.76 1986.93,3222.76
  region net VM: 3434.27,3554.82 3452.27,3554.82 3448.27,3546.42 3438.27,3546.42
  region net VM: 3250.24,3182 3237.52,3194.73 3246.29,3197.84 3253.36,3190.77
  region net BM_CLK: 2950.34,4228.75 2950.33,4246.75 2941.93,4242.75 2941.93,4232.75
  region net CH15: 3078.76,3288.88 3072.8,3271.9 3066.02,3277.94 3069.69,3288.4
  region net CH15: 2910.33,3478.76 2910.33,3496.76 2901.93,3492.76 2901.93,3482.76
  region net BAT+: 3641.83,4083.75 3641.81,4101.75 3633.42,4097.75 3633.42,4087.75
  region net BAT+: 3640.9,4171.57 3640.86,4189.57 3632.47,4185.55 3632.49,4175.55
  region net CH8: 3840.34,3863.75 3840.33,3881.75 3831.93,3877.75 3831.93,3867.75
  region net CH7: 3843.93,3814.45 3843.92,3832.45 3835.53,3828.45 3835.53,3818.45
  region net CH10: 3856.21,4386.75 3856.2,4368.75 3861.77,4372.75 3861.77,4382.75
  region net CH9: 3950.26,4384.97 3932.26,4384.98 3936.27,4393.38 3946.27,4393.37
  region net VCC_MCU: 3648.99,3944.98 3636.24,3932.27 3645,3929.15 3652.08,3936.21
  region net VCC_MCU: 3637.74,3932.27 3625.03,3945.02 3621.91,3936.26 3628.97,3929.17
  region net VCC_MCU: 3845.34,3913.75 3845.33,3931.75 3836.93,3927.75 3836.93,3917.75
  region net VCC_MCU: 3530.31,4239.58 3516.28,4228.3 3514.11,4237.34 3521.95,4243.64
  region net VCC_MCU: 3491.5,3945.02 3478.8,3932.27 3487.57,3929.17 3494.63,3936.26
  region net VCC_MCU: 3085.34,3868.75 3085.33,3886.75 3076.93,3882.75 3076.93,3872.75
  region net BAT+: 3194.71,3105.69 3176.71,3105.7 3180.71,3114.1 3190.71,3114.09
  region net BAT+: 3197.69,3098.48 3184.93,3085.78 3193.69,3082.65 3200.78,3089.71
  region net BAT+: 3251.21,3993.76 3251.2,4011.76 3259.61,4007.76 3259.6,3997.76
  region net BAT+: 3203.57,4081.61 3198.08,4098.75 3207.22,4097.75 3210.43,4087.75
  region net VCC_MCU: 3717.74,3110.39 3699.77,3109.28 3704.27,3101.14 3714.27,3101.76
  region net VCC_MCU: 3717,3125.99 3715.34,3108.06 3724.07,3111.25 3725,3121.25
  region net VCC_MCU: 3708.76,3129.75 3696.31,3116.74 3693.01,3125.44 3699.92,3132.67
  region net CH5: 3834.27,3324.82 3852.27,3324.82 3848.27,3316.42 3838.27,3316.42
  region net CH6: 3835.34,3373.75 3835.33,3391.75 3826.93,3387.75 3826.93,3377.75
  region net VCC_MCU: 3859.42,3432.7 3846.71,3419.96 3855.48,3416.86 3862.55,3423.94
  region net VCC_MCU: 3932.54,2800.99 3919.8,2788.28 3916.7,2797.05 3923.78,2804.11
  region net CH15: 3989.27,2919.82 4007.27,2919.82 4003.27,2911.42 3993.27,2911.42
  region net U2_5: 2589.27,3154.82 2607.27,3154.82 2603.27,3146.42 2593.27,3146.42
  region net U2_6: 2660.81,3163.57 2646.85,3152.21 2655.23,3148.2 2663.03,3154.55
  region net U2_7: 2710.4,3209.71 2697.71,3196.95 2706.48,3193.86 2713.54,3200.95
  region net CH14: 2435.24,2473.5 2422.52,2486.24 2431.29,2489.34 2438.36,2482.27
  region net CH14: 2415.34,2465.25 2415.33,2483.25 2406.93,2479.25 2406.93,2469.25
  region net CH14: 2474.27,2555.62 2492.27,2555.62 2488.27,2547.22 2478.27,2547.22
  region net CH13: 2509.95,2483.25 2509.94,2465.25 2518.34,2469.25 2518.35,2479.25
  region net VCC_MCU: 2590.27,2407.52 2577,2419.69 2585.63,2423.18 2593,2416.41
  region net VCC_MCU: 2572.69,2397.13 2568.42,2414.62 2561.01,2409.56 2563.79,2398.2
  region net VCC_MCU: 3013.29,2574.73 3000.55,2562.02 2997.45,2570.8 3004.53,2577.86
  region net VCC_MCU: 3004.59,2553.75 3004.58,2571.75 2996.19,2567.75 2996.19,2557.75
  region net CH11: 1963.3,2481.75 1950.57,2469.02 1947.46,2477.78 1954.53,2484.86
  region net CH11: 1970.5,2478.76 1970.47,2460.76 1978.88,2464.75 1978.89,2474.75
  region net CH12: 1875.88,2460.76 1875.86,2478.76 1867.46,2474.75 1867.48,2464.75
  region net VCC_MCU: 2043.51,2395.76 2031.33,2409.02 2027.85,2400.4 2034.61,2393.02
  region net VCC_MCU: 2055.24,2406.94 2040.96,2395.98 2049.22,2391.73 2057.22,2397.87
  region net VCC_NRF: 3300.34,3353.75 3300.33,3371.75 3291.93,3367.75 3291.93,3357.75
  region net VCC_NRF: 3575.24,3362 3562.52,3374.73 3571.29,3377.84 3578.36,3370.77
  region net BAT+: 1909.27,2920.69 1927.27,2920.69 1923.27,2929.09 1913.27,2929.09
  region net BAT+: 2015.24,2903.5 2002.51,2890.78 2011.28,2887.67 2018.35,2894.73
  region net PPM: 2714.27,3540.69 2732.27,3540.69 2728.27,3549.09 2718.27,3549.09
  region net PPM: 2376.21,3948.76 2376.2,3966.76 2384.61,3962.76 2384.6,3952.76
  region net TX_BM_DT: 2700.24,3542 2687.52,3554.73 2696.29,3557.84 2703.36,3550.77
  region net VCC_MCU: 2074.02,4179.73 2061.29,4167 2058.18,4175.77 2065.25,4182.84
  region net VCC_MCU: 2202.44,4133.66 2202.41,4115.66 2210.82,4119.65 2210.84,4129.65
  region net TX_BM_DT: 1959.51,4335.77 1977.51,4335.77 1973.51,4344.17 1963.51,4344.17
  region net TX_BM_DT: 2137.74,4058.37 2125.03,4071.12 2121.91,4062.36 2128.97,4055.27
  region net VCC_MCU: 2845.24,3447 2832.52,3459.73 2841.29,3462.84 2848.36,3455.77
  region net VCC_MCU: 2834.02,3459.73 2821.29,3447 2818.18,3455.77 2825.25,3462.84
  region net VCC_MCU: 2834.02,3435.78 2821.29,3448.51 2818.18,3439.74 2825.25,3432.67
  region net VCC_MCU: 2579.18,3382.43 2566.45,3395.16 2575.22,3398.27 2582.29,3391.2
  region net VCC_MCU: 2625.34,3683.75 2625.33,3701.75 2616.93,3697.75 2616.93,3687.75
  region net VCC_MCU: 2769.27,3509.82 2787.27,3509.82 2783.27,3502.76 2773.27,3502.76
  region net VCC_MCU: 3861.92,2916.18 3849.2,2928.91 3857.23,2931.29 3864.3,2924.22
  region net VCC_MCU: 3964.02,2929.73 3951.29,2917 3949.73,2924.22 3956.8,2931.29
  region net VCC_MCU: 3149.02,3700.78 3136.29,3713.51 3133.18,3704.74 3140.25,3697.67
  region net VCC_MCU: 3117.29,3430.35 3104.56,3417.63 3101.45,3426.39 3108.52,3433.47
  region net VCC_MCU: 3107.54,3426.31 3125.54,3426.31 3121.54,3434.71 3111.54,3434.71
  region net VCC_LCD: 2805.24,4272 2792.52,4284.73 2801.29,4287.84 2808.36,4280.77
  region net VCC_LCD: 2785.34,4263.75 2785.33,4281.75 2776.93,4277.75 2776.93,4267.75
  region net USB1_3: 2119.35,3634.85 2137.35,3634.85 2133.35,3626.45 2123.35,3626.45
  region net USB1_3: 2054.27,3495.69 2072.27,3495.69 2068.27,3504.09 2058.27,3504.09
  region net RX_BM_SW: 3099.27,4525.69 3117.27,4525.69 3113.27,4534.09 3103.27,4534.09
  region net VCC_MCU: 3560.24,3112 3547.52,3124.73 3556.29,3127.84 3563.36,3120.77
  region net U2_5: 2681.85,3046.89 2669.12,3034.17 2666.01,3042.93 2673.08,3050.01
  region net U2_6: 2775.55,3047.69 2762.82,3034.96 2759.71,3043.73 2766.78,3050.8
  region net CH11: 1922.47,2618.31 1940.47,2618.31 1936.47,2609.91 1926.47,2609.91
  region net VCC_MCU: 2081.73,3726.95 2064.04,3709.29 2079.96,3703.98 2087.04,3711.05
  region net VCC_MCU: 3022.09,2740.25 3022.09,2715.25 3007.09,2722.75 3007.09,2732.75
  region net U2_7: 3112.2,2749.41 3124.44,2727.61 3130.88,2746.79 3125.79,2755.84
  region net U2_7: 3155.07,2763.53 3180.07,2763.53 3172.57,2748.53 3162.57,2748.53
  region net U2_7: 3125.81,2805.55 3125.81,2780.55 3114.27,2788.05 3114.27,2798.05
  region net U2_7: 3128.05,2763.53 3153.05,2763.53 3132.62,2748.53 3118.47,2748.53
  region net D4_1: 2727.05,3989.45 2727.05,4014.45 2742.05,4006.95 2742.05,3996.95
  region net D4_1: 2725.77,4026.56 2700.77,4026.56 2708.27,4041.56 2718.27,4041.56
  region net R12_2: 2738.17,3878.95 2763.17,3878.95 2755.67,3863.95 2745.67,3863.95
  region net BEEPER: 2701.46,3831.74 2689.04,3810.04 2702.68,3803.67 2707.82,3812.66
  region net R12_2: 2756.57,3845.47 2738.17,3845.47 2745.67,3860.47 2755.67,3860.47
  region net D4_1: 2889.11,3874.4 2866.77,3874.4 2854.54,3889.4 2868.68,3889.4
  region net VCC_LCD: 2889.11,4028 2866.77,4028 2854.54,4043 2868.68,4043
  region net BAT+: 3414.96,4397.13 3389.96,4397.46 3375.3,4382.65 3389.26,4382.47
  region net BAT+: 3427.69,4397.13 3450.99,4397.13 3462.26,4382.13 3448.12,4382.13
  region net VCC_MCU: 3427.63,4318.38 3450.99,4318.38 3462.2,4303.38 3448.06,4303.38
  region net VCC_NRF: 3266.23,4318.38 3289.57,4318.38 3300.8,4303.38 3286.66,4303.38
  region net BAT+: 3492.06,4357.76 3468.7,4357.76 3457.49,4372.76 3471.63,4372.76
  region net BAT+: 3486.77,4318.38 3511.77,4318.38 3504.27,4306.55 3494.27,4306.55
  region net BAT+: 3128.15,4357.76 3104.87,4357.76 3125.3,4372.76 3139.45,4372.76
  region net BAT+: 3349.76,4357.76 3324.76,4357.76 3315.19,4372.76 3329.33,4372.76
  region net BAT+: 3368.31,4357.76 3344.98,4357.76 3365.41,4372.76 3379.55,4372.76
  region net VCC_LCD: 3163.87,4318.38 3188.87,4318.38 3181.37,4303.38 3171.37,4303.38
  region net VCC_MCU: 2213.78,4112.15 2213.78,4137.15 2228.78,4129.65 2228.78,4119.65
  region net BM_CLK: 2213.78,4168.05 2213.78,4193.05 2228.78,4185.55 2228.78,4175.55
  region net BM_CLK: 2200.19,4164.84 2178.35,4177 2171.88,4163.43 2180.97,4158.37
  region net TX_BM_DT: 2158.66,3971.3 2180.35,3983.74 2161.29,3990.1 2152.3,3984.95
  region net VCC_MCU: 2194.1,4014.55 2194.1,4038.86 2209.1,4032.05 2209.1,4022.05
  region net TX_BM_DT: 2276.77,3943.65 2276.77,3968.65 2291.77,3961.15 2291.77,3951.15
  region net TX_BM_DT: 2233.47,3968.65 2233.47,3943.65 2218.47,3951.15 2218.47,3961.15
  region net VCC_MCU: 2233.47,4039.55 2233.47,4014.55 2218.47,4022.05 2218.47,4032.05
  region net VCC_MCU: 2255.08,4046.73 2276.77,4034.3 2283.14,4047.95 2274.15,4053.1
  region net VCC_MCU: 2262.6,4130.98 2262.6,4112.15 2247.6,4119.65 2247.6,4129.65
  region net VCC_MCU: 2305.9,4103.82 2284.09,4091.61 2303.28,4085.16 2312.35,4090.24
  region net VCC_MCU: 2271.77,4091.61 2296.77,4091.61 2289.27,4076.61 2279.27,4076.61
  region net BM_CLK: 2262.6,4193.05 2262.6,4168.05 2247.6,4175.55 2247.6,4185.55
  region net BM_CLK: 2284.19,4201.85 2305.9,4189.46 2312.28,4203.09 2303.28,4208.23
  region net U2_7: 3180.07,2674.72 3155.07,2674.72 3162.57,2689.72 3172.57,2689.72
  region net VCC_NRF: 3247.67,3350.25 3247.67,3375.25 3262.67,3367.75 3262.67,3357.75
  region net NRF_CE: 3247.67,3400.95 3247.67,3425.95 3262.67,3418.45 3262.67,3408.45
  region net NRF_CSN: 3247.67,3459.65 3247.67,3483.15 3262.67,3494.22 3262.67,3480.08
  region net NRF_CSN: 3247.67,3459.65 3247.67,3483.15 3262.67,3494.22 3262.67,3480.08
  region net NRF_SCK: 3247.67,3500.95 3247.67,3525.95 3248.97,3518.45 3248.97,3508.45
  region net NRF_MOSI: 3247.67,3554.65 3247.67,3579.65 3262.67,3589.22 3262.67,3575.08
  region net NRF_MISO: 3247.67,3604.65 3247.67,3629.65 3262.67,3639.22 3262.67,3625.08
  region net VCC_NRF: 3968.77,3765.05 3943.77,3765.05 3951.27,3780.05 3961.27,3780.05
  region net VCC_NRF: 3916.97,3728.95 3916.97,3705.95 3901.97,3694.38 3901.97,3708.52
  region net CH8: 3658.66,3868.75 3658.66,3893.75 3673.66,3886.25 3673.66,3876.25
  region net VCC_MCU: 3658.66,3936.74 3636.83,3924.56 3656.04,3918.1 3665.12,3923.16
  region net VCC_MCU: 3637.06,3924.56 3615.35,3936.96 3608.98,3923.33 3617.98,3918.19
  region net CH5: 3709.11,3198.91 3730.94,3186.73 3737.4,3200.31 3728.32,3205.37
  region net CH5: 3687.63,3191.75 3687.63,3166.75 3672.63,3174.25 3672.63,3184.25
  region net VCC_MCU: 3696.77,3096.55 3721.77,3096.55 3714.27,3081.55 3704.27,3081.55
  region net VCC_MCU: 3730.94,3103.75 3730.94,3128.75 3745.94,3121.25 3745.94,3111.25
  region net VCC_MCU: 3687.63,3123.62 3709.4,3135.92 3690.26,3142.33 3681.22,3137.22
  region net CH5: 3652.2,3166.75 3652.2,3191.75 3667.2,3184.25 3667.2,3174.25
  region net CH6: 3489.45,3171.1 3489.45,3191.75 3504.45,3184.25 3504.45,3174.25
  region net CH6: 3551.61,3198.91 3573.46,3186.78 3579.94,3200.34 3570.85,3205.39
  region net CH6: 3530.15,3191.75 3530.15,3166.75 3515.15,3174.25 3515.15,3184.25
  region net VCC_MCU: 3551.61,3135.92 3573.46,3123.78 3579.94,3137.35 3570.84,3142.4
  region net CH8: 3737.4,3861.57 3737.4,3885.25 3752.4,3877.75 3752.4,3867.75
  region net CH8: 3694.09,3893.75 3694.09,3868.75 3679.09,3876.25 3679.09,3886.25
  region net CH7: 3579.92,3873.83 3558.14,3861.57 3577.3,3855.14 3586.35,3860.24
  region net CH7: 3536.61,3893.75 3536.61,3868.75 3521.61,3876.25 3521.61,3886.25
  region net CH7: 3501.18,3868.75 3501.18,3893.75 3516.18,3886.25 3516.18,3876.25
  region net VCC_MCU: 3501.18,3936.96 3479.47,3924.56 3498.56,3918.19 3507.56,3923.33
  region net CH10: 3921.57,4298.12 3933.76,4319.95 3920.19,4326.4 3915.12,4317.33
  region net CH10: 3928.77,4276.64 3953.77,4276.64 3946.27,4261.64 3936.27,4261.64
  region net CH10: 3953.77,4241.21 3928.77,4241.21 3936.27,4256.21 3946.27,4256.21
  region net CH9: 3953.77,4398.69 3928.77,4398.69 3936.27,4413.69 3946.27,4413.69
  region net CH9: 3928.77,4434.12 3953.77,4434.12 3946.27,4419.12 3936.27,4419.12
  region net CH12: 1862.16,2482.25 1862.16,2457.25 1847.16,2464.75 1847.16,2474.75
  region net VCC_MCU: 1905.46,2399.18 1883.58,2387.09 1902.85,2380.6 1911.96,2385.63
  region net CH12: 1826.72,2457.25 1826.72,2482.25 1841.72,2474.75 1841.72,2464.75
  region net CH11: 1940.89,2477.16 1962.66,2489.46 1943.52,2495.87 1934.48,2490.76
  region net CH11: 1984.2,2457.25 1984.2,2482.25 1999.2,2474.75 1999.2,2464.75
  region net CH11: 2019.64,2482.25 2019.64,2457.25 2004.64,2464.75 2004.64,2474.75
  region net VCC_MCU: 2041.42,2387.09 2019.64,2399.35 2013.21,2385.76 2022.26,2380.67
  region net VCC_MCU: 2062.94,2399.24 2041.09,2387.09 2060.32,2380.62 2069.42,2385.67
  region net CH14: 2423.16,2493.94 2444.92,2481.64 2451.34,2495.25 2442.3,2500.35
  region net CH14: 2401.61,2486.75 2401.61,2461.75 2386.61,2469.25 2386.61,2479.25
  region net VCC_MCU: 2444.92,2403.83 2423.13,2391.58 2442.3,2385.14 2451.35,2390.23
  region net VCC_MCU: 2403.14,2391.58 2428.14,2391.58 2407.76,2376.58 2393.65,2376.58
  region net CH14: 2366.18,2461.75 2366.18,2486.75 2381.18,2479.25 2381.18,2469.25
  region net CH13: 2523.66,2461.75 2523.66,2486.75 2538.66,2479.25 2538.66,2469.25
  region net CH13: 2559.09,2486.75 2559.09,2461.75 2544.09,2469.25 2544.09,2479.25
  region net VCC_MCU: 2580.68,2430.95 2602.4,2418.57 2608.79,2432.2 2599.78,2437.33
  region net VCC_MCU: 2559.09,2413.07 2559.09,2391.58 2544.09,2378.5 2544.09,2392.64
  region net CH15: 4010.77,2889.41 3985.77,2889.41 3993.27,2904.41 4003.27,2904.41
  region net CH15: 3982.27,2846.1 4007.27,2846.1 3999.77,2831.1 3989.77,2831.1
  region net CH15: 4007.27,2810.67 3982.27,2810.67 3989.77,2825.67 3999.77,2825.67
  region net VCC_MCU: 3912.09,2788.94 3924.46,2810.67 3910.83,2817.05 3905.7,2808.04
  region net BAT+: 3355.61,4080.25 3355.61,4105.25 3340.61,4097.75 3340.61,4087.75
  region net BAT+: 3489.33,4105.25 3489.32,4080.25 3504.33,4087.75 3504.33,4097.75
  region net BAT+: 3294.61,4080.25 3294.6,4105.25 3279.61,4097.75 3279.61,4087.75
  region net BAT+: 3361.33,4105.25 3361.32,4080.25 3376.33,4087.75 3376.33,4097.75
  region net VCC_LCD: 3297.78,4165.38 3322.78,4165.64 3302.35,4180.64 3288.21,4180.64
  region net BAT+: 3582.9,4080.25 3582.9,4105.25 3567.9,4097.75 3567.9,4087.75
  region net BAT+: 3521.9,4080.25 3521.89,4105.25 3506.9,4097.75 3506.9,4087.75
  region net BAT+: 3588.62,4105.25 3588.61,4080.25 3603.62,4087.75 3603.62,4097.75
  region net VCC_NRF: 3514.69,4156.29 3537.88,4165.64 3517.45,4180.64 3503.3,4180.64
  region net VCC_NRF: 3580.79,4164.36 3580.77,4139.36 3595.78,4146.85 3595.78,4156.85
  region net BAT+: 3262.64,4078.87 3260.25,4103.76 3275.9,4097.75 3276.86,4087.75
  region net VCC_MCU: 3095.1,4133.08 3070.1,4133.33 3060.53,4118.08 3074.67,4118.08

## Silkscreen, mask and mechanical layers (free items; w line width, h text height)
Top Overlay:
  lines w10 net S$11530: 4133.07,2330.98 4133.07,4743.58
  lines w10 net S$11535: 4467.71,2319.17 5553.54,2319.17
  text "GND" at 1833.86,4698.35 h31.5
  text "3V3" at 1936.22,4698.32 h31.5
  text "TX" at 2046.46,4698.35 h31.5
  text "RX" at 2144.88,4698.34 h31.5
  text "BT3-4" at 2440.16,4698.32 h31.5
  text "EC11" at 3014.96,4698.32 h31.5
  text "BT1-2" at 3554.33,4698.34 h31.5
  text "GND" at 1717.72,4523.11 h31.5
  text "GND" at 3739.37,4482.55 h27.56
  text "GND" at 2639.37,4477.04 h27.56
  text "GND" at 3184.25,4477.04 h27.56
  text "GND" at 1837.8,4452.24 h31.5
  text "PPM" at 1944.1,4452.24 h31.5
  text "V" at 3783.97,4428.49 h27.56 r159
  text "4R-L" at 2372.44,4411.29 h27.56
  text "3U-D" at 2502.36,4411.29 h27.56
  text "CLK" at 2928.27,4411.29 h27.56
  text "DT" at 3032.28,4411.29 h27.56
  text "SW" at 3089.76,4411.29 h27.56
  text "2U-D" at 3479.53,4411.29 h27.56
  text "1R-L" at 3600,4411.29 h27.56
  text "TFT" at 1802.7,4397.91 h45 r270
  text "10" at 3766.93,4351.85 h27.56
  text "9" at 3781.53,4329.36 h27.56 r185
  text "G" at 3780.23,4284.41 h27.56 r180
  text "CH9-10" at 4097.64,4275.07 h31.5 r90
  text "Y1" at 1995.28,3958.15 h27.56
  text "104" at 3137.01,3930.59 h27.56
  text "V" at 3766.93,3921.14 h27.56 r180
  text "1" at 1822.05,3883.35 h27.56 r180
  text "8" at 3766.93,3873.11 h27.56 r180
  text "1K" at 1999.22,3863.66 h27.56
  text "104" at 2566.15,3828.23 h27.56
  text "7" at 3766.93,3822.71 h27.56 r180
  text "CH7-8" at 4097.62,3782.16 h31.5 r90
  text "G" at 3764.57,3773.11 h27.56 r180
  text "SWD" at 2112.6,3695.1 h45
  text "4K7" at 2176.38,3623.5 h27.56
  text "20R" at 2176.38,3540.82 h27.56
  text "20R" at 2176.38,3454.21 h27.56
  text "V" at 3768.21,3433.41 h27.56 r159
  text "104" at 2369.29,3410.9 h27.56
  text "6" at 3762.07,3384.28 h27.56 r185
  text "5" at 3763.27,3334.33 h27.56 r180
  text "1K" at 2517.32,3317.2 h27.56
  text "1K" at 2302.36,3313.26 h27.56
  text "104" at 3215.75,3308.54 h27.56
  text "CH5-6" at 4097.66,3291.61 h31.5 r90
  text "G" at 3763.27,3289.33 h27.56 r180
  text "TC4056" at 1814.18,3273.11 h27.56
  text "STM32F103RCT6" at 2628.35,3219.56 h27.56
  text "B+" at 1719.69,3216.02 h31.5
  text "SW" at 1818.11,3216.02 h31.5
  text "10K" at 3083.46,3172.32 h27.56
  text "BT0" at 3302.37,3142.48 h27.56
  text "VCC" at 3403.27,3142.48 h27.56
  text "20K" at 3072.23,3091.22 h27.56
  text "1K2" at 1932.25,3002.96 h27.56
  text "10K" at 3083.46,2998.3 h27.56
  text "10uF*2" at 2030.71,2985.71 h27.56
  text "AT24C32D" at 2477.05,2985.55 h27.56 r90
  text "B-" at 1723.62,2956.18 h31.5
  text "10K" at 3083.46,2918.78 h27.56
  text "V" at 3780.31,2918.41 h27.56 r159
  text "BT1" at 3307.96,2885.06 h27.56
  text "GND" at 3403.27,2885.06 h27.56
  text "1K" at 2030.29,2861.96 h27.56
  text "15" at 3763.27,2841.77 h27.56
  text "1K" at 1921.26,2839.25 h27.56
  text "CSTCE8M00G52" at 2593.7,2832.16 h27.56
  text "16" at 3764.57,2791.77 h27.56
  text "G" at 3776.57,2774.33 h27.56 r180
  text "CH16-CH15" at 4097.66,2721.53 h31.5 r90
  text "G" at 1843.31,2643.98 h27.56 r180
  text "G" at 2372.44,2643.98 h27.56 r180
  text "V" at 2525.2,2643.98 h27.56 r180
  text "G" at 2908.27,2644.33 h27.56 r180
  text "1" at 2963.27,2644.33 h27.56 r180
  text "G" at 3058.27,2644.33 h27.56 r180
  text "2" at 3108.27,2644.33 h27.56 r180
  text "G" at 3538.27,2644.33 h27.56 r180
  text "3" at 3593.27,2644.33 h27.56 r180
  text "G" at 3688.27,2644.33 h27.56 r180
  text "V" at 2003.21,2643.41 h27.56 r159
  text "V" at 3013.21,2643.41 h27.56 r159
  text "V" at 3158.21,2643.41 h27.56 r159
  text "V" at 3633.33,2643.41 h27.56 r201
  text "V" at 3788.21,2643.41 h27.56 r159
  text "4" at 3746.37,2641.7 h27.56 r144
  text "11-12" at 1883.47,2616.42 h27.56
  text "13-14" at 2407.09,2616.42 h27.56
  text "1" at 4357.48,2497.91 h47.24 r180
  text "CH11-CH12" at 1841.73,2317.6 h31.5
  text "CH13-CH14" at 2337.01,2315.26 h31.5
  text "CH1-CH2" at 2940.16,2315.23 h31.5
  text "CH3-CH4" at 3565.35,2315.23 h31.5
  text "GND" at 4576.98,2039.98 h31.5
  text "SW" at 4576.98,1938.09 h31.5
  text "DT" at 4576.98,1836.59 h31.5
  text "GND" at 4576.98,1739.59 h31.5
  text "CLK" at 4576.98,1634.98 h31.5
Bottom Overlay:
  lines w10 net S$11530: 4133.07,2330.98 4133.07,4743.58
  lines w10 net S$11535: 4467.71,2319.17 5553.54,2319.17
  text "10uF*6" at 3038.58,4349.48 h27.56
  text "BUZ" at 2759.05,4346.33 h27.56
  text "ME6209A33*3" at 3411.02,4188.07 h27.56
  text "10K*4" at 3895.27,4176.26 h27.56
  text "10K" at 2129.14,4168.38 h27.56
  text "104" at 2402.36,4161.29 h27.56
  text "10K" at 2125.99,3999.09 h27.56
  text "104" at 2364.57,3995.94 h27.56
  text "Y1" at 2622.84,3927.44 h27.56
  text "D1" at 2981.1,3880.98 h27.56
  text "1" at 1704.65,3845.55 h47.24 r270
  text "10K*4" at 3425.98,3846.33 h27.56
  text "1K" at 2626.77,3802.24 h27.56
  text "1.8寸TFT液晶屏" at 5155.52,3525.27 h80
  text "J20RC_PRO_MINI_V2" at 2994.49,3484.92 h59.05
  text "2021.02.20" at 2994.49,3345.55 h59.05
  text "10K*4" at 3671.65,3019.56 h27.56
  text "10K*2" at 3885.04,2838.46 h27.56
  text "10K" at 2991.34,2699.88 h27.56
  text "104" at 3263.78,2558.94 h27.56
  text "1" at 4396.06,2451.46 h47.24
  text "10K*4" at 2204.73,2402.24 h27.56
  text "10K*4" at 2751.18,2402.24 h27.56
  text "GND" at 4654.15,2039.19 h31.5
  text "SW" at 4654.15,1937.3 h31.5
  text "EC11旋转编码器" at 5309.27,1853.37 h80
  text "DT" at 4654.15,1835.8 h31.5
  text "GND" at 4654.15,1738.8 h31.5
  text "CLK" at 4654.15,1634.19 h31.5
